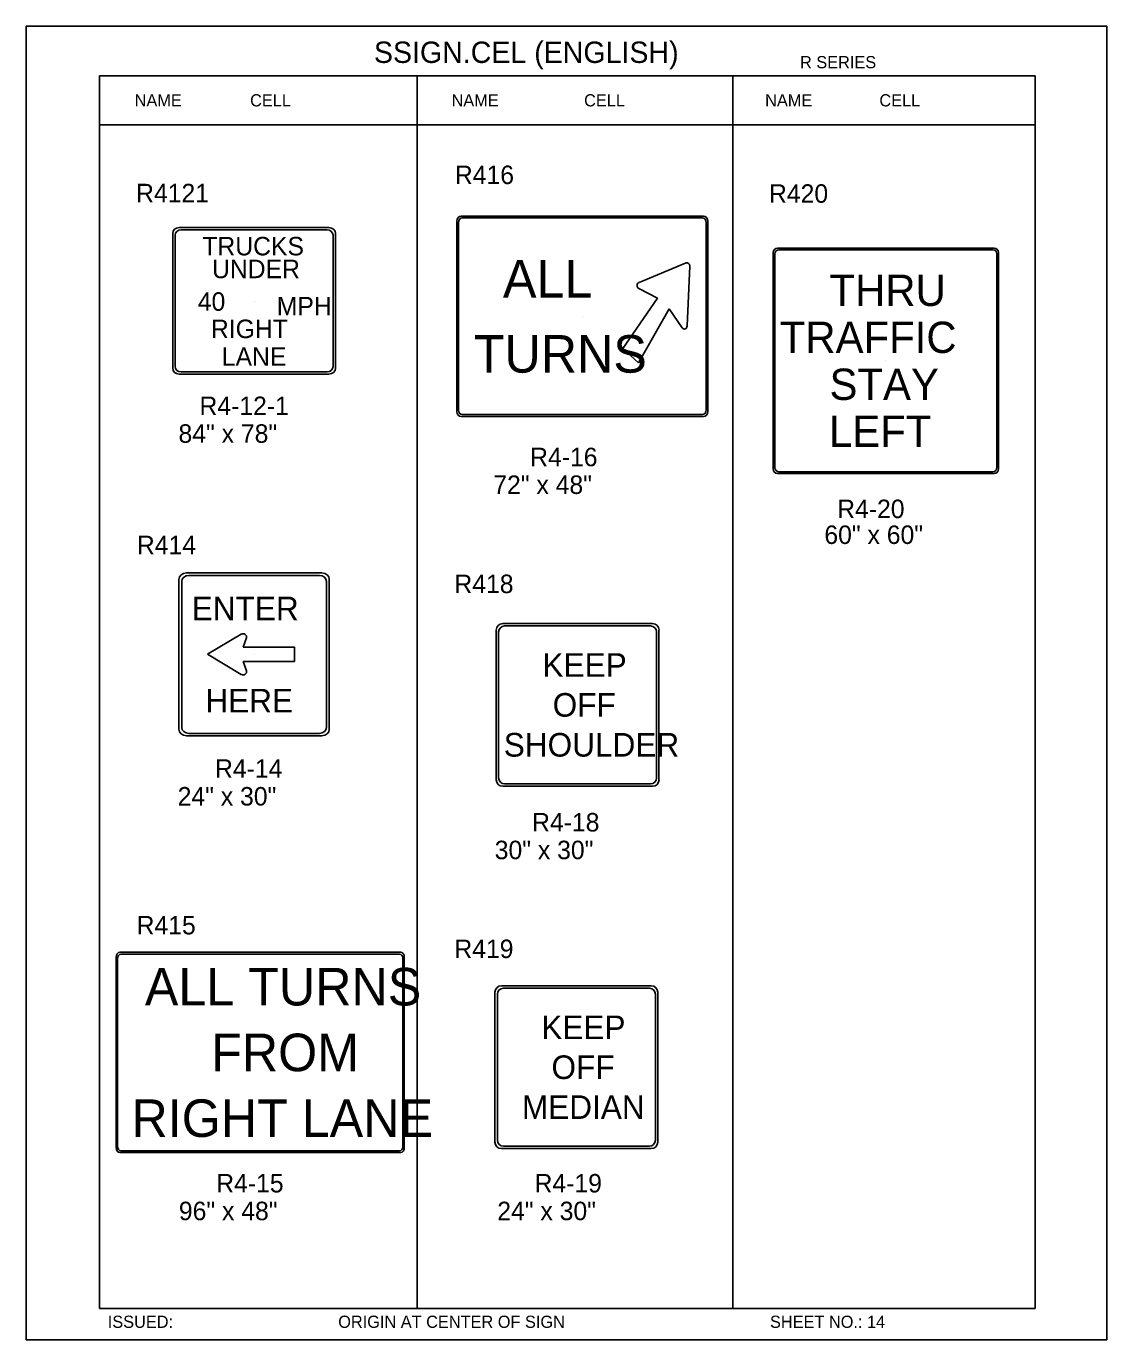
# Model space of a CAD drawing. Extents: x -5299 to 22597, y -19549 to -1808.
# Drawn here: x -4475 to -3774, y -5466 to -4614 of the extents above; entities that cross this region are included whole.
import ezdxf

# ---------------------------------------------------------------- set-up
doc = ezdxf.new("R2010")
doc.units = 0
for name, color, linetype in [('Level 1', 7, 'Continuous'), ('Level 2', 7, 'Continuous'), ('Level 3', 7, 'Continuous'), ('Level 63', 7, 'Continuous')]:
    doc.layers.add(name, color=color, linetype=linetype)

msp = doc.modelspace()

# ---------------------------------------------------------------- linework, layer by layer
at = {"layer": 'Level 1'}
for p, q in [((-3820.56, -4645.77), (-4427.57, -4645.77)), ((-4427.57, -4645.77), (-4427.57, -5445.77)), ((-4221.37, -4645.77), (-4221.37, -5445.77)), ((-4016.74, -4645.77), (-4016.74, -5445.77)), ((-3820.56, -4645.77), (-3820.56, -5445.77)), ((-3820.56, -4677.44), (-4427.57, -4677.44)), ((-4192.15, -4737.98), (-4036.36, -4737.98)), ((-4374.61, -4745.63), (-4279.91, -4745.63)), ((-4194.66, -4862.6), (-4194.66, -4740.99)), ((-4033.85, -4740.99), (-4033.85, -4862.6)), ((-4378.52, -4834.39), (-4378.52, -4749.15)), ((-4276, -4749.15), (-4276, -4834.39)), ((-3989.39, -4900.02), (-3989.39, -4761.31)), ((-3986.68, -4758.6), (-3847.97, -4758.6)), ((-3845.27, -4761.31), (-3845.27, -4900.02)), ((-4077.49, -4779.83), (-4046.93, -4767.19)), ((-4044.61, -4769.32), (-4046.26, -4808.05)), ((-4088.05, -4822.8), (-4065.55, -4790.11)), ((-4065.55, -4790.11), (-4077.62, -4783.78)), ((-4327.14, -4792.28), (-4327.14, -4792.28)), ((-4057.9, -4797.05), (-4077.84, -4831.95)), ((-4049.41, -4809.33), (-4057.9, -4797.05)), ((-4114.26, -4801.8), (-4114.26, -4801.8)), ((-4077.84, -4831.95), (-4088.05, -4822.8)), ((-3917.33, -4830.67), (-3917.33, -4830.67)), ((-4279.91, -4837.9), (-4374.61, -4837.9)), ((-4036.36, -4865.61), (-4192.15, -4865.61)), ((-3847.97, -4902.73), (-3986.68, -4902.73)), ((-4374.19, -5068.56), (-4374.19, -4973.86)), ((-4369.68, -4969.95), (-4284.79, -4969.95)), ((-4280.28, -4973.86), (-4280.28, -5068.56)), ((-4164.72, -5002.72), (-4070.01, -5002.72)), ((-4335.68, -5008.14), (-4357.44, -5021.12)), ((-4334.35, -5016.52), (-4332.24, -5010.44)), ((-4168.62, -5101.33), (-4168.62, -5006.63)), ((-4066.1, -5006.63), (-4066.1, -5101.33)), ((-4301.03, -5016.52), (-4334.35, -5016.52)), ((-4301.03, -5025.79), (-4301.03, -5016.52)), ((-4357.44, -5021.12), (-4335.75, -5034.17)), ((-4332.24, -5031.87), (-4334.43, -5025.79)), ((-4334.43, -5025.79), (-4301.03, -5025.79)), ((-4327.23, -5021.21), (-4327.23, -5021.21)), ((-4117.36, -5053.98), (-4117.36, -5053.98)), ((-4284.79, -5072.47), (-4369.68, -5072.47)), ((-4070.01, -5105.24), (-4164.72, -5105.24)), ((-4413.71, -5215.7), (-4232.83, -5215.7)), ((-4415.87, -5340.32), (-4415.87, -5218.7)), ((-4230.67, -5218.7), (-4230.67, -5340.32)), ((-4169.41, -5336.46), (-4169.41, -5241.76)), ((-4165.5, -5237.85), (-4070.8, -5237.85)), ((-4066.89, -5241.76), (-4066.89, -5336.46)), ((-4323.27, -5279.51), (-4323.27, -5279.51)), ((-4118.15, -5289.11), (-4118.15, -5289.11)), ((-4232.83, -5343.33), (-4413.71, -5343.33)), ((-4070.8, -5340.37), (-4165.5, -5340.37)), ((-4427.57, -5445.77), (-3820.56, -5445.77))]:
    msp.add_line(p, q, dxfattribs=at)
for centre, radius, start, end in [((-3986.68, -4761.31), 2.71, 90, 180), ((-3847.97, -4761.31), 2.71, 0, 90), ((-3986.68, -4900.02), 2.71, 180, 270), ((-3847.97, -4900.02), 2.71, 270, 0), ((-4164.72, -5006.63), 3.91, 90, 180), ((-4164.72, -5101.33), 3.91, 180, 270), ((-4070.01, -5101.33), 3.91, 270, 0), ((-4165.5, -5241.76), 3.91, 90, 180), ((-4070.8, -5241.76), 3.91, 0, 90), ((-4165.5, -5336.46), 3.91, 180, 270), ((-4070.8, -5336.46), 3.91, 270, 0)]:
    msp.add_arc(centre, radius, start, end, dxfattribs=at)
for centre, major_axis, ratio, start_param, end_param in [((-4192.15, -4740.99), (0, -3.01), 0.83475, 3.141593, 4.712389), ((-4036.36, -4740.99), (0, 3.01), 0.83475, 4.712389, 6.283185), ((-4374.61, -4749.15), (-3.91, 0), 0.9, 4.712389, 6.283185), ((-4279.91, -4749.15), (-3.91, 0), 0.9, 3.141593, 4.712389), ((-4046.37, -4769.23), (0, -2.14), 0.83475, 1.527577, 3.478447), ((-4076.98, -4781.83), (0, -2.12), 0.83475, 3.451897, 5.881452), ((-4048.05, -4807.94), (0, 2.12), 0.83475, 2.250511, 4.671837), ((-4374.61, -4834.38), (3.91, 0), 0.9, 3.141593, 4.712389), ((-4279.91, -4834.38), (3.91, 0), 0.9, 4.712389, 6.283185), ((-4192.15, -4862.6), (0, -3.01), 0.83475, 4.712389, 6.283185), ((-4036.36, -4862.6), (0, 3.01), 0.83475, 3.141593, 4.712389), ((-4369.68, -4973.86), (-4.51, 0), 0.866667, 4.712389, 6.283185), ((-4284.79, -4973.86), (-4.51, 0), 0.866667, 3.141593, 4.712389), ((-4334.49, -5009.88), (2.37, 0), 0.866667, 6.014589, 8.386103), ((-4334.51, -5032.42), (-2.39, 0), 0.866667, 1.019875, 3.40872), ((-4369.68, -5068.56), (4.51, 0), 0.866667, 3.141593, 4.712389), ((-4284.79, -5068.56), (4.51, 0), 0.866667, 4.712389, 6.283185), ((-4413.71, -5218.71), (0, -3.01), 0.71875, 3.141593, 4.712389), ((-4232.83, -5218.71), (0, 3.01), 0.71875, 4.712389, 6.283185), ((-4413.71, -5340.32), (0, -3.01), 0.71875, 4.712389, 6.283185), ((-4232.83, -5340.32), (0, 3.01), 0.71875, 3.141593, 4.712389)]:
    msp.add_ellipse(centre, major_axis=major_axis, ratio=ratio, start_param=start_param, end_param=end_param, dxfattribs=at)
at = {"layer": 'Level 3'}
for p, q in [((-4192.96, -4736.77), (-4035.56, -4736.77)), ((-4278.66, -4744.22), (-4375.86, -4744.22)), ((-4195.67, -4863.57), (-4195.67, -4740.03)), ((-4032.84, -4740.03), (-4032.84, -4863.57)), ((-4380.09, -4748.03), (-4380.09, -4835.51)), ((-4274.43, -4835.51), (-4274.43, -4748.03)), ((-3990.48, -4900.89), (-3990.48, -4760.44)), ((-3987.55, -4757.52), (-3847.11, -4757.52)), ((-3844.18, -4760.44), (-3844.18, -4900.89)), ((-4375.86, -4839.32), (-4278.66, -4839.32)), ((-4035.56, -4866.82), (-4192.96, -4866.82)), ((-3847.11, -4903.82), (-3987.55, -4903.82)), ((-4283.34, -4968.38), (-4371.12, -4968.38)), ((-4376, -4972.61), (-4376, -5069.81)), ((-4278.47, -5069.81), (-4278.47, -4972.61)), ((-4165.97, -5001.15), (-4068.76, -5001.15)), ((-4170.19, -5102.58), (-4170.19, -5005.38)), ((-4064.54, -5005.38), (-4064.54, -5102.58)), ((-4371.12, -5074.04), (-4283.34, -5074.04)), ((-4068.76, -5106.81), (-4165.97, -5106.81)), ((-4414.4, -5214.49), (-4232.14, -5214.49)), ((-4416.74, -5341.28), (-4416.74, -5217.74)), ((-4229.81, -5217.74), (-4229.81, -5341.28)), ((-4170.98, -5240.5), (-4170.98, -5337.71)), ((-4069.55, -5236.28), (-4166.75, -5236.28)), ((-4065.32, -5337.71), (-4065.32, -5240.5)), ((-4166.75, -5341.94), (-4069.55, -5341.94)), ((-4232.14, -5344.53), (-4414.4, -5344.53))]:
    msp.add_line(p, q, dxfattribs=at)
for centre, radius, start, end in [((-3987.55, -4760.44), 2.93, 90, 180), ((-3847.11, -4760.44), 2.93, 0, 90), ((-3987.55, -4900.89), 2.93, 180, 270), ((-3847.11, -4900.89), 2.93, 270, 0), ((-4165.97, -5005.38), 4.23, 90, 180), ((-4070.01, -5006.63), 3.91, 0, 90), ((-4068.76, -5005.38), 4.23, 0, 90), ((-4165.97, -5102.58), 4.23, 180, 270), ((-4068.76, -5102.58), 4.23, 270, 0), ((-4166.75, -5240.5), 4.23, 90, 180), ((-4069.55, -5240.5), 4.23, 0, 90), ((-4166.75, -5337.71), 4.23, 180, 270), ((-4069.55, -5337.71), 4.23, 270, 0)]:
    msp.add_arc(centre, radius, start, end, dxfattribs=at)
for centre, major_axis, ratio, start_param, end_param in [((-4192.96, -4740.03), (0, -3.25), 0.83475, 3.141593, 4.712389), ((-4035.56, -4740.03), (0, 3.25), 0.83475, 4.712389, 6.283185), ((-4375.86, -4748.03), (-4.23, 0), 0.9, 4.712389, 6.283185), ((-4278.66, -4748.03), (-4.23, 0), 0.9, 3.141593, 4.712389), ((-4375.86, -4835.51), (4.23, 0), 0.9, 3.141593, 4.712389), ((-4278.66, -4835.51), (4.23, 0), 0.9, 4.712389, 6.283185), ((-4192.96, -4863.56), (0, -3.25), 0.83475, 4.712389, 6.283185), ((-4035.56, -4863.56), (0, 3.25), 0.83475, 3.141593, 4.712389), ((-4371.12, -4972.61), (-4.88, 0), 0.866667, 4.712389, 6.283185), ((-4283.34, -4972.61), (-4.88, 0), 0.866667, 3.141593, 4.712389), ((-4371.12, -5069.81), (4.88, 0), 0.866667, 3.141593, 4.712389), ((-4283.34, -5069.81), (4.88, 0), 0.866667, 4.712389, 6.283185), ((-4414.4, -5217.74), (0, -3.25), 0.71875, 3.141593, 4.712389), ((-4232.14, -5217.74), (0, 3.25), 0.71875, 4.712389, 6.283185), ((-4414.4, -5341.28), (0, -3.25), 0.71875, 4.712389, 6.283185), ((-4232.14, -5341.28), (0, 3.25), 0.71875, 3.141593, 4.712389)]:
    msp.add_ellipse(centre, major_axis=major_axis, ratio=ratio, start_param=start_param, end_param=end_param, dxfattribs=at)
at = {"layer": 'Level 63'}
msp.add_lwpolyline([(-4475.08, -5465.96), (-3774.03, -5465.96), (-3774.03, -4613.58), (-4475.08, -4613.58)], close=True, dxfattribs=at)

# ---------------------------------------------------------------- texts
at = {"layer": 'Level 1'}
for s, height, p in [('TRUCKS', 12, (-4360.86, -4762.27)), ('UNDER', 12, (-4354.58, -4777.06)), ('ALL', 24.383, (-4165.78, -4789.6)), ('THRU', 20.319, (-3953.89, -4795.11)), ('40', 12, (-4363.78, -4798.23)), ('MPH', 12, (-4312.55, -4801.18)), ('RIGHT', 12, (-4355.27, -4815.94)), ('TRAFFIC', 20.319, (-3986.16, -4825.59)), ('TURNS', 24.383, (-4184.73, -4838.37)), ('LANE', 12, (-4348.22, -4833.92)), ('STAY', 20.319, (-3953.89, -4856.07)), ('LEFT', 20.319, (-3954.21, -4886.54)), ('ENTER', 15.321, (-4367.74, -4999.08)), ('KEEP', 15.321, (-4140.13, -5035.75)), ('HERE', 15.321, (-4358.9, -5058.89)), ('OFF', 15.321, (-4133.54, -5061.64)), ('SHOULDER', 15.321, (-4165.28, -5087.53)), ('ALL TURNS', 24.383, (-4398.14, -5249.03)), ('KEEP', 15.321, (-4140.91, -5270.88)), ('FROM', 24.383, (-4355.15, -5291.7)), ('OFF', 15.321, (-4134.32, -5296.77)), ('RIGHT LANE', 24.383, (-4406.83, -5334.37)), ('MEDIAN', 15.321, (-4153.49, -5322.65))]:
    msp.add_text(s, height=height, dxfattribs=at).set_placement(p)
at = {"layer": 'Level 2'}
for s, p in [('R416', (-4196.98, -4715.98)), ('R4121', (-4403.82, -4727.83)), ('R420', (-3993.17, -4728.14)), ('R414', (-4403.31, -4956.19)), ('R418', (-4197.3, -4981.44)), ('R415', (-4403.49, -5202.94)), ('R419', (-4197.32, -5218.26))]:
    msp.add_text(s, height=12, dxfattribs=at).set_placement(p)
at = {"layer": 'Level 3'}
for s, height, p in [('SSIGN.CEL (ENGLISH)', 13.8566, (-4249.5, -4637.38)), ('R SERIES', 7.918, (-3973.06, -4640.82)), ('NAME', 7.918, (-4404.76, -4665.6)), ('CELL', 7.918, (-4329.85, -4665.6)), ('NAME', 7.918, (-4199.15, -4665.6)), ('CELL', 7.918, (-4113.14, -4665.6)), ('NAME', 7.918, (-3995.66, -4665.6)), ('CELL', 7.918, (-3921.54, -4665.6)), ('R4-12-1', 12, (-4362.7, -4865.88)), ('84" x 78"', 12, (-4376.31, -4883.88)), ('R4-16', 12, (-4148.16, -4899.09)), ('72" x 48"', 12, (-4172.06, -4917.09)), ('R4-20', 12, (-3948.93, -4932.77)), ('60" x 60"', 12, (-3957.24, -4949.55)), ('R4-14', 12, (-4352.61, -5101.29)), ('24" x 30"', 12, (-4376.85, -5119.29)), ('R4-18', 12, (-4146.89, -5136.12)), ('30" x 30"', 12, (-4171.12, -5154.12)), ('R4-15', 12, (-4351.83, -5370.39)), ('R4-19', 12, (-4145.28, -5370.39)), ('96" x 48"', 12, (-4376.07, -5388.39)), ('24" x 30"', 12, (-4169.47, -5388.39)), ('ISSUED:', 7.918, (-4422.21, -5458.26)), ('ORIGIN AT CENTER OF SIGN', 7.9181, (-4272.68, -5458.26)), ('SHEET NO.: 14', 7.918, (-3992.52, -5458.26))]:
    msp.add_text(s, height=height, dxfattribs=at).set_placement(p)

doc.saveas('drawing.dxf')
